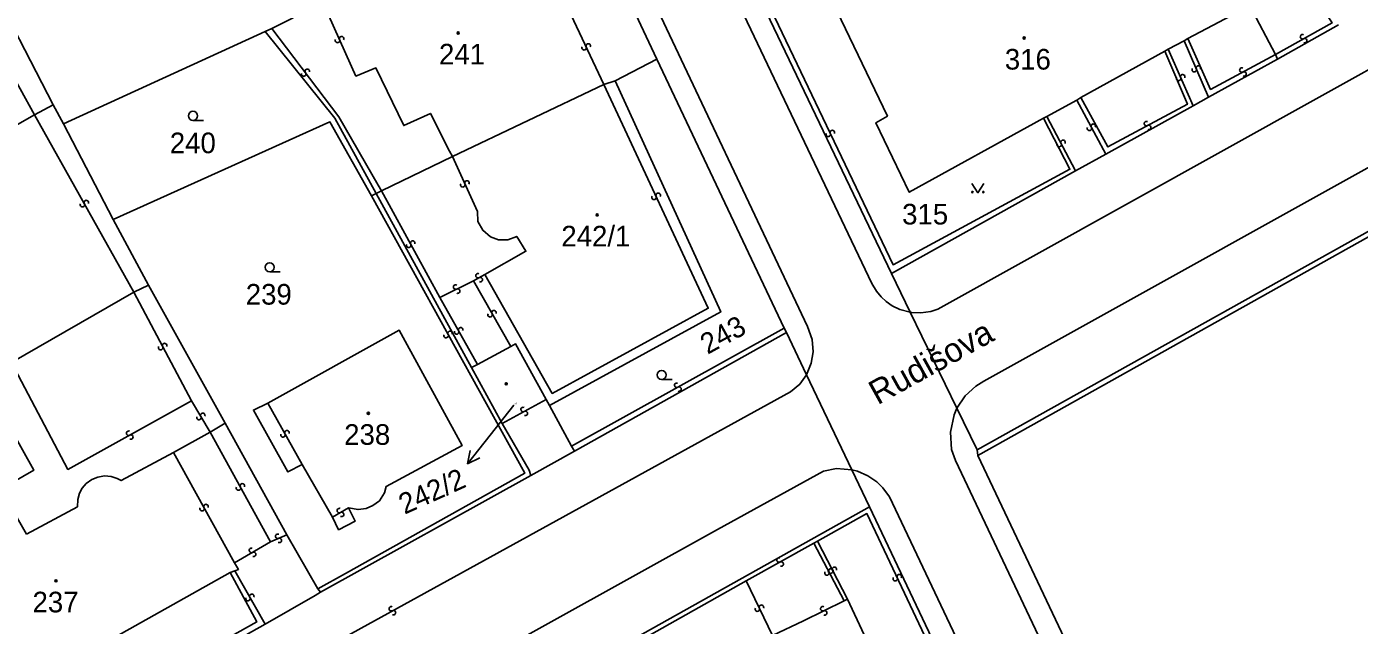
# Model space of a CAD drawing. Extents: x -600391 to -599491, y -1160176 to -1159402.
# Drawn here: x -600227.7 to -600117.8, y -1159850.4 to -1159801.1 of the extents above; entities that cross this region are included whole.
import ezdxf

# ---------------------------------------------------------------- set-up
doc = ezdxf.new("R2010")
doc.units = 0
for name, color, linetype in [('Level 1', 7, 'Continuous'), ('Level 11', 7, 'Continuous'), ('Level 13', 7, 'Continuous'), ('Level 3', 7, 'Continuous'), ('Level 4', 7, 'Continuous'), ('Level 5', 7, 'Continuous'), ('Level 57', 7, 'Continuous')]:
    doc.layers.add(name, color=color, linetype=linetype)

msp = doc.modelspace()

# ---------------------------------------------------------------- linework, layer by layer
at = {"layer": 'Level 1'}
for points in [[(-600149.33, -1159835.93), (-600066.93, -1159789.91)], [(-600231.06, -1159796.68), (-600225.47, -1159807.52)], [(-600162.28, -1159796.91), (-600156.73, -1159808.45), (-600157.7, -1159809.01), (-600154.94, -1159814.73), (-600143.87, -1159808.62)], [(-600175.73, -1159803.75), (-600178.55, -1159797.71)], [(-600156.4, -1159821.41), (-600167.03, -1159799.22)], [(-600207.44, -1159801.23), (-600203.96, -1159799.47)], [(-600131.97, -1159802.07), (-600126.86, -1159799.38)], [(-600126.86, -1159799.38), (-600124.77, -1159803.38)], [(-600208, -1159801.49), (-600207.44, -1159801.23)], [(-600119.56, -1159800.94), (-600124.58, -1159803.76)], [(-600224.63, -1159809.1), (-600208, -1159801.49)], [(-600198.85, -1159814.83), (-600202.26, -1159808.62), (-600208, -1159801.49)], [(-600133.6, -1159802.95), (-600132.29, -1159802.24)], [(-600132.29, -1159802.24), (-600131.97, -1159802.07)], [(-600140.79, -1159806.92), (-600133.87, -1159803.11)], [(-600133.87, -1159803.11), (-600133.6, -1159802.95)], [(-600124.77, -1159803.38), (-600124.58, -1159803.76)], [(-600179.16, -1159805.54), (-600175.73, -1159803.75)], [(-600165.24, -1159825.92), (-600175.73, -1159803.75)], [(-600124.58, -1159803.76), (-600130.27, -1159806.89)], [(-600184.58, -1159832.3), (-600170.47, -1159824.58), (-600179.16, -1159805.54)], [(-600180.1, -1159805.85), (-600179.16, -1159805.54)], [(-600192.58, -1159811.78), (-600180.1, -1159805.85)], [(-600130.27, -1159806.89), (-600131.54, -1159807.61)], [(-600227, -1159808.35), (-600225.47, -1159807.52)], [(-600225.47, -1159807.52), (-600224.63, -1159809.1)], [(-600143.61, -1159808.48), (-600141.12, -1159807.15)], [(-600141.12, -1159807.15), (-600140.79, -1159806.92)], [(-600131.54, -1159807.61), (-600138.73, -1159811.58)], [(-600236.99, -1159814.01), (-600227, -1159808.35)], [(-600220.53, -1159816.97), (-600224.63, -1159809.1)], [(-600199.25, -1159815.01), (-600202.67, -1159808.93), (-600220.53, -1159816.97)], [(-600143.87, -1159808.62), (-600143.61, -1159808.48)], [(-600198.42, -1159814.6), (-600192.58, -1159811.78)], [(-600138.73, -1159811.58), (-600141.23, -1159812.95)], [(-600141.23, -1159812.95), (-600156.4, -1159821.41)], [(-600198.85, -1159814.83), (-600199.25, -1159815.01)], [(-600198.85, -1159814.83), (-600198.42, -1159814.6)], [(-600190.99, -1159829.17), (-600198.85, -1159814.83)], [(-600217.61, -1159822.39), (-600220.53, -1159816.97)], [(-600156.4, -1159821.41), (-600154.85, -1159824.6)], [(-600228.91, -1159828.75), (-600218.81, -1159822.96)], [(-600218.81, -1159822.96), (-600217.61, -1159822.39)], [(-600211.3, -1159833.74), (-600217.61, -1159822.39)], [(-600154.85, -1159824.6), (-600151, -1159832.5)], [(-600207.79, -1159832.1), (-600196.96, -1159826.09), (-600191.77, -1159835.57), (-600198.02, -1159838.95), (-600198.18, -1159839.49), (-600198.59, -1159840.13), (-600199.13, -1159840.53), (-600199.69, -1159840.77), (-600200.35, -1159840.86), (-600201.14, -1159840.72)], [(-600182.52, -1159836.05), (-600165.06, -1159826.28)], [(-600165.06, -1159826.28), (-600165.24, -1159825.92)], [(-600163.4, -1159829.75), (-600165.06, -1159826.28)], [(-600187.77, -1159827.44), (-600190.52, -1159828.9)], [(-600184.86, -1159831.79), (-600187.37, -1159827.21), (-600187.77, -1159827.44)], [(-600190.52, -1159828.9), (-600190.99, -1159829.17)], [(-600188.47, -1159833.77), (-600190.99, -1159829.17)], [(-600159.66, -1159837.59), (-600163.4, -1159829.75)], [(-600204.95, -1159837.14), (-600206.13, -1159837.76), (-600208.97, -1159832.67), (-600207.79, -1159832.1)], [(-600184.58, -1159832.3), (-600184.86, -1159831.79)], [(-600182.75, -1159835.64), (-600184.58, -1159832.3)], [(-600151, -1159832.5), (-600149.33, -1159835.93)], [(-600212.52, -1159834.48), (-600211.3, -1159833.74)], [(-600206.23, -1159842.93), (-600211.3, -1159833.74)], [(-600188.47, -1159833.77), (-600186.24, -1159837.62), (-600186.12, -1159838.06)], [(-600215.56, -1159836.16), (-600212.52, -1159834.48)], [(-600227.68, -1159842.88), (-600223.47, -1159840.63), (-600223.45, -1159840.03), (-600223.3, -1159839.51), (-600223.07, -1159839.09), (-600222.75, -1159838.72), (-600222.28, -1159838.38), (-600221.8, -1159838.18), (-600221.24, -1159838.09), (-600220.7, -1159838.14), (-600220.19, -1159838.3), (-600219.88, -1159838.48), (-600215.56, -1159836.16)], [(-600186.12, -1159838.06), (-600182.52, -1159836.05)], [(-600182.52, -1159836.05), (-600182.75, -1159835.64)], [(-600149.28, -1159836.42), (-600149.33, -1159835.93)], [(-600122.68, -1159892.59), (-600149.28, -1159836.42)], [(-600202.46, -1159841.48), (-600204.95, -1159837.14)], [(-600158.21, -1159840.64), (-600159.66, -1159837.59)], [(-600203.43, -1159847.67), (-600186.12, -1159838.06)], [(-600201.14, -1159840.72), (-600200.59, -1159841.82), (-600201.95, -1159842.52), (-600202.46, -1159841.48)], [(-600158.21, -1159840.64), (-600178.06, -1159851.76)], [(-600148.19, -1159861.76), (-600158.21, -1159840.64)], [(-600203.65, -1159847.4), (-600206.23, -1159842.93)], [(-600203.43, -1159847.67), (-600203.65, -1159847.4)], [(-600208.01, -1159850.29), (-600203.89, -1159847.95), (-600203.43, -1159847.67)], [(-600227.9, -1159861.47), (-600208.01, -1159850.29)]]:
    msp.add_lwpolyline(points, dxfattribs=at)
at = {"layer": 'Level 13'}
for centre, start, end in [((-600202.04, -1159802.22), 151.6005, 23.6985), ((-600201.7, -1159802.08), 331.386, 203.976), ((-600181.38, -1159802.67), 332.4757, 204.5737), ((-600122.53, -1159801.92), 66.4794, 298.5774), ((-600122.35, -1159802.24), 246.2649, 118.8549), ((-600181.72, -1159802.83), 152.2613, 24.8513), ((-600204.53, -1159804.76), 344.3292, 216.9192), ((-600131.45, -1159804.63), 150.6388, 23.2288), ((-600131.11, -1159804.49), 330.8533, 202.9513), ((-600127.53, -1159804.66), 65.7119, 297.8099), ((-600204.83, -1159804.98), 164.5437, 36.6417), ((-600132.74, -1159805.35), 151.0066, 23.5966), ((-600132.4, -1159805.21), 331.221, 203.319), ((-600127.35, -1159804.98), 245.4974, 118.0874), ((-600139.77, -1159809.28), 335.7197, 207.8177), ((-600135.39, -1159809.07), 65.3442, 297.9342), ((-600161.61, -1159809.96), 152.9224, 25.0204), ((-600161.27, -1159809.8), 332.7079, 205.2979), ((-600140.09, -1159809.46), 155.5053, 28.0953), ((-600135.21, -1159809.39), 245.5586, 117.6566), ((-600142.58, -1159810.8), 155.1908, 27.7808), ((-600142.26, -1159810.62), 335.4053, 207.5033), ((-600191.72, -1159814.11), 151.874, 23.972), ((-600191.38, -1159813.96), 331.6595, 204.2495), ((-600223.06, -1159815.75), 156.6466, 28.7446), ((-600222.74, -1159815.57), 336.4322, 209.0222), ((-600175.96, -1159815.14), 152.199, 24.789), ((-600175.62, -1159814.98), 332.4135, 204.5114), ((-600195.85, -1159818.91), 335.8965, 208.4865), ((-600196.17, -1159819.09), 156.1109, 28.2089), ((-600190.46, -1159821.6), 65.8157, 297.9137), ((-600190.28, -1159821.92), 245.6012, 118.1912), ((-600192.3, -1159822.53), 63.8544, 295.9524), ((-600192.14, -1159822.87), 243.6399, 116.2299), ((-600189.15, -1159824.64), 336.9808, 209.0788), ((-600189.47, -1159824.82), 156.7664, 29.3564), ((-600193.09, -1159826.53), 156.1277, 28.7177), ((-600192.77, -1159826.35), 336.3421, 208.4401), ((-600192.22, -1159826.23), 156.5772, 28.6752), ((-600191.9, -1159826.05), 336.3628, 208.9528), ((-600216.61, -1159827.52), 155.2288, 27.3268), ((-600216.29, -1159827.35), 335.0144, 207.6044), ((-600174.09, -1159830.62), 66.1934, 298.7834), ((-600173.91, -1159830.94), 246.4079, 118.5059), ((-600213.46, -1159833.28), 158.4162, 31.0062), ((-600213.14, -1159833.1), 338.6306, 210.7286), ((-600186.75, -1159832.62), 66.1165, 298.2145), ((-600186.57, -1159832.94), 245.902, 118.492), ((-600206.21, -1159834.53), 336.5592, 209.1492), ((-600219.25, -1159834.57), 66.3843, 298.4823), ((-600219.07, -1159834.89), 246.1698, 118.7598), ((-600206.53, -1159834.71), 156.7736, 28.8716), ((-600209.88, -1159838.91), 336.0984, 208.1964), ((-600210.2, -1159839.09), 155.8839, 28.4739), ((-600213.2, -1159840.79), 156.1647, 28.7547), ((-600212.88, -1159840.61), 336.3792, 208.4771), ((-600201.89, -1159840.94), 67.3042, 299.4022), ((-600201.71, -1159841.26), 247.0898, 119.6798), ((-600206.97, -1159843.06), 61.6542, 293.7522), ((-600209.13, -1159844.23), 67.5328, 299.6308), ((-600206.83, -1159843.4), 241.4397, 114.0297), ((-600208.95, -1159844.55), 247.3183, 119.9083), ((-600165.66, -1159845.02), 66.6278, 298.7258), ((-600165.48, -1159845.34), 246.4134, 119.0034), ((-600161.71, -1159846.08), 154.6782, 27.2682), ((-600161.42, -1159845.94), 154.2958, 26.8858), ((-600161.39, -1159845.92), 334.8926, 206.9906), ((-600161.1, -1159845.78), 334.5102, 206.6082), ((-600155.75, -1159846.39), 332.7096, 204.8076), ((-600156.09, -1159846.55), 152.4951, 25.0851), ((-600209.42, -1159848.19), 156.7762, 29.3662), ((-600209.1, -1159848.01), 336.9907, 209.0887), ((-600197.61, -1159849.03), 66.1805, 298.2785), ((-600197.43, -1159849.35), 245.9661, 118.5561), ((-600167.45, -1159849.06), 153.1134, 25.2114), ((-600167.11, -1159848.9), 332.899, 205.489), ((-600162.06, -1159849.03), 63.5926, 295.6906), ((-600161.9, -1159849.37), 243.3782, 115.9682)]:
    msp.add_arc(centre, 0.184, start, end, dxfattribs=at)
at = {"layer": 'Level 3'}
for points in [[(-600154.85, -1159824.6), (-600155.7, -1159824.37), (-600156.33, -1159824.07), (-600156.83, -1159823.72), (-600157.25, -1159823.34), (-600157.63, -1159822.87), (-600158.01, -1159822.25), (-600225.11, -1159681.41), (-600225.5, -1159680.26), (-600225.71, -1159678.98), (-600225.76, -1159677.2), (-600225.55, -1159675.64)], [(-600236.3, -1159676.88), (-600235.69, -1159677.1), (-600234.79, -1159677.54), (-600233.86, -1159678.21), (-600233.01, -1159679.1), (-600232.25, -1159680.16), (-600163.31, -1159825.79), (-600162.94, -1159826.86), (-600162.86, -1159827.88), (-600163.01, -1159828.81), (-600163.4, -1159829.75)], [(-600072.76, -1159779.78), (-600074.27, -1159780.8), (-600152.58, -1159824.35), (-600153.16, -1159824.54), (-600153.99, -1159824.66), (-600154.73, -1159824.62), (-600154.85, -1159824.6)], [(-600069.02, -1159786.29), (-600070.06, -1159786.51), (-600148.78, -1159830.29), (-600149.46, -1159830.71), (-600150.34, -1159831.49), (-600151, -1159832.5)], [(-600149.28, -1159836.42), (-600066.99, -1159790.34), (-600036.77, -1159845.39)], [(-600232.95, -1159797.62), (-600227, -1159808.35)], [(-600192.58, -1159811.78), (-600192.81, -1159811.33), (-600194.39, -1159808.23), (-600196.59, -1159809.23), (-600198.88, -1159804.48), (-600200.52, -1159805.15), (-600203.22, -1159799.15)], [(-600143.87, -1159808.62), (-600141.69, -1159812.83), (-600156.27, -1159820.7), (-600166.61, -1159799.07)], [(-600183, -1159799.66), (-600180.1, -1159805.85)], [(-600124.77, -1159803.38), (-600120.1, -1159800.78), (-600120.36, -1159800.37), (-600120.03, -1159800.16)], [(-600198.42, -1159814.6), (-600198.69, -1159814.14), (-600201.92, -1159808.51), (-600207.44, -1159801.23)], [(-600132.29, -1159802.24), (-600130.27, -1159806.89)], [(-600131.97, -1159802.07), (-600130.11, -1159806.26), (-600124.77, -1159803.38)], [(-600133.87, -1159803.11), (-600132.02, -1159807.48), (-600138.57, -1159810.99), (-600140.79, -1159806.92)], [(-600133.6, -1159802.95), (-600131.54, -1159807.61)], [(-600180.1, -1159805.85), (-600171.49, -1159824.28), (-600184.35, -1159831.3), (-600189.89, -1159821.5)], [(-600141.12, -1159807.15), (-600138.73, -1159811.58)], [(-600218.81, -1159822.96), (-600227, -1159808.35)], [(-600143.61, -1159808.48), (-600141.23, -1159812.95)], [(-600189.89, -1159821.5), (-600186.52, -1159819.58), (-600187.28, -1159818.36), (-600188.02, -1159818.65), (-600188.77, -1159818.64), (-600189.43, -1159818.41), (-600190.08, -1159817.86), (-600190.49, -1159817.13), (-600190.52, -1159816.3), (-600192.58, -1159811.78)], [(-600199.25, -1159815.01), (-600186.6, -1159837.86), (-600201.39, -1159846.13), (-600203.65, -1159847.4)], [(-600193.6, -1159823.39), (-600198.42, -1159814.6)], [(-600193.6, -1159823.39), (-600190.85, -1159822.02)], [(-600190.85, -1159822.02), (-600189.89, -1159821.5)], [(-600190.85, -1159822.02), (-600187.77, -1159827.44)], [(-600214.08, -1159831.91), (-600218.81, -1159822.96)], [(-600190.52, -1159828.9), (-600193.6, -1159823.39)], [(-600165.24, -1159825.92), (-600182.75, -1159835.64)], [(-600228.91, -1159828.75), (-600224.25, -1159837.55), (-600214.08, -1159831.91)], [(-600230.31, -1159867.23), (-600164.72, -1159831.16), (-600163.95, -1159830.52), (-600163.4, -1159829.75)], [(-600231.24, -1159830.17), (-600227.07, -1159837.62), (-600229.77, -1159839.19), (-600227.68, -1159842.88)], [(-600214.08, -1159831.91), (-600212.52, -1159834.48)], [(-600204.95, -1159837.14), (-600207.79, -1159832.1)], [(-600188.47, -1159833.77), (-600184.86, -1159831.79)], [(-600058.2, -1160028.15), (-600058.36, -1160028.15), (-600059, -1160028.11), (-600059.48, -1160028.02), (-600059.94, -1160027.88), (-600060.54, -1160027.6), (-600093.98, -1159957.52), (-600113.29, -1159916.73), (-600151.13, -1159836.81), (-600151.44, -1159835.9), (-600151.54, -1159834.48), (-600151.24, -1159833.05), (-600151, -1159832.5)], [(-600212.52, -1159834.48), (-600207.56, -1159843.53)], [(-600215.56, -1159836.16), (-600210.52, -1159845.25)], [(-600226.79, -1159873.6), (-600170.72, -1159842.51), (-600161.99, -1159837.7), (-600160.92, -1159837.49), (-600159.66, -1159837.59)], [(-600159.66, -1159837.59), (-600159.21, -1159837.71), (-600158.35, -1159838.08), (-600157.61, -1159838.58), (-600157.12, -1159839.07), (-600156.56, -1159839.81), (-600136.86, -1159881.35), (-600099.49, -1159960.35), (-600082.51, -1159996.2), (-600082.35, -1159996.48), (-600082.21, -1159996.87), (-600082.15, -1159997.28), (-600082.21, -1159997.74), (-600082.31, -1159998.06), (-600082.48, -1159998.38), (-600082.79, -1159998.74), (-600083.08, -1159998.96), (-600083.18, -1159999.01)], [(-600202.46, -1159841.48), (-600201.14, -1159840.72)], [(-600162.48, -1159843.47), (-600158.42, -1159841.19), (-600153.42, -1159851.75)], [(-600207.56, -1159843.53), (-600206.23, -1159842.93)], [(-600210.52, -1159845.25), (-600207.56, -1159843.53)], [(-600168.36, -1159846.74), (-600162.79, -1159843.62)], [(-600162.79, -1159843.62), (-600162.48, -1159843.47)], [(-600162.79, -1159843.62), (-600160.31, -1159848.38)], [(-600162.48, -1159843.47), (-600160.03, -1159848.25)], [(-600210.52, -1159845.25), (-600210.21, -1159845.79), (-600210.5, -1159845.91)], [(-600210.89, -1159846.04), (-600230.39, -1159856.96)], [(-600210.89, -1159846.04), (-600208.7, -1159850.11), (-600228.09, -1159860.95)], [(-600210.5, -1159845.91), (-600210.89, -1159846.04)], [(-600210.5, -1159845.91), (-600208.01, -1159850.29)], [(-600168.36, -1159846.74), (-600177.69, -1159851.97), (-600166.99, -1159870.82)], [(-600166.2, -1159851.22), (-600168.36, -1159846.74)], [(-600166.2, -1159851.22), (-600163.64, -1159850.02), (-600160.31, -1159848.38)], [(-600160.31, -1159848.38), (-600160.03, -1159848.25)], [(-600160.03, -1159848.25), (-600157.46, -1159853.7)]]:
    msp.add_lwpolyline(points, dxfattribs=at)
at = {"layer": 'Level 5'}
for p, q in [((-600213.95, -1159808.81), (-600213.08, -1159808.81)), ((-600207.63, -1159821.28), (-600206.76, -1159821.28)), ((-600175.34, -1159830.15), (-600174.46, -1159830.15))]:
    msp.add_line(p, q, dxfattribs=at)
msp.add_lwpolyline([(-600149.78, -1159814.01), (-600149.28, -1159814.76), (-600148.78, -1159814.01)], dxfattribs=at)
for centre, radius in [((-600192.1, -1159801.6), 0.09), ((-600192.1, -1159801.6), 0.0521), ((-600145.47, -1159802.02), 0.09), ((-600145.47, -1159802.02), 0.0521), ((-600213.95, -1159808.43), 0.375), ((-600149.73, -1159814.71), 0.05), ((-600148.83, -1159814.71), 0.05), ((-600180.65, -1159816.59), 0.09), ((-600180.65, -1159816.59), 0.0521), ((-600207.63, -1159820.9), 0.375), ((-600175.34, -1159829.77), 0.375), ((-600188.14, -1159830.5), 0.09), ((-600188.14, -1159830.5), 0.0521), ((-600199.5, -1159832.93), 0.09), ((-600199.5, -1159832.93), 0.0521), ((-600225.24, -1159846.73), 0.09), ((-600225.24, -1159846.73), 0.0521)]:
    msp.add_circle(centre, radius, dxfattribs=at)
at = {"layer": 'Level 57'}
for p, q in [((-600187.52, -1159832.27), (-600189.47, -1159834.74)), ((-600189.47, -1159834.74), (-600191.33, -1159837.09))]:
    msp.add_line(p, q, dxfattribs=at)
msp.add_lwpolyline([(-600190.32, -1159836.61), (-600191.33, -1159837.09), (-600191.1, -1159836)], dxfattribs=at)

# ---------------------------------------------------------------- texts
at = {"layer": 'Level 11'}
msp.add_text('Rudišova', height=2, rotation=29.0141, dxfattribs=at).set_placement((-600157.54, -1159832.28))
at = {"layer": 'Level 4'}
for s, p in [('241', (-600193.68, -1159804.2)), ('316', (-600147.06, -1159804.62)), ('240', (-600215.86, -1159811.51)), ('315', (-600155.52, -1159817.38)), ('242/1', (-600183.6, -1159819.19)), ('239', (-600209.6, -1159823.98)), ('238', (-600201.49, -1159835.53)), ('237', (-600227.17, -1159849.33))]:
    msp.add_text(s, height=1.7, dxfattribs=at).set_placement(p)
for s, height, rotation, p in [('243', 1.7, 28.8, (-600171.55, -1159828.12)), ('242/2', 0.1, 24.3, (-600187.52, -1159832.27))]:
    msp.add_text(s, height=height, rotation=rotation, dxfattribs=at).set_placement(p)
at = {"layer": 'Level 57'}
msp.add_text('242/2', height=1.7, rotation=24.3, dxfattribs=at).set_placement((-600196.51, -1159841.29))

doc.saveas('drawing.dxf')
